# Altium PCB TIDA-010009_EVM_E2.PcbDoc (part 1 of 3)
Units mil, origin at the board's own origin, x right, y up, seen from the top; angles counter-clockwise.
Board outline 4485 x 3050 mil, 4 copper layers (Top Layer, Signal Layer 1, Signal Layer 2, Bottom Layer), stack 61.634 mil thick; 216 components, 95 nets, 514 pads, 224 vias.
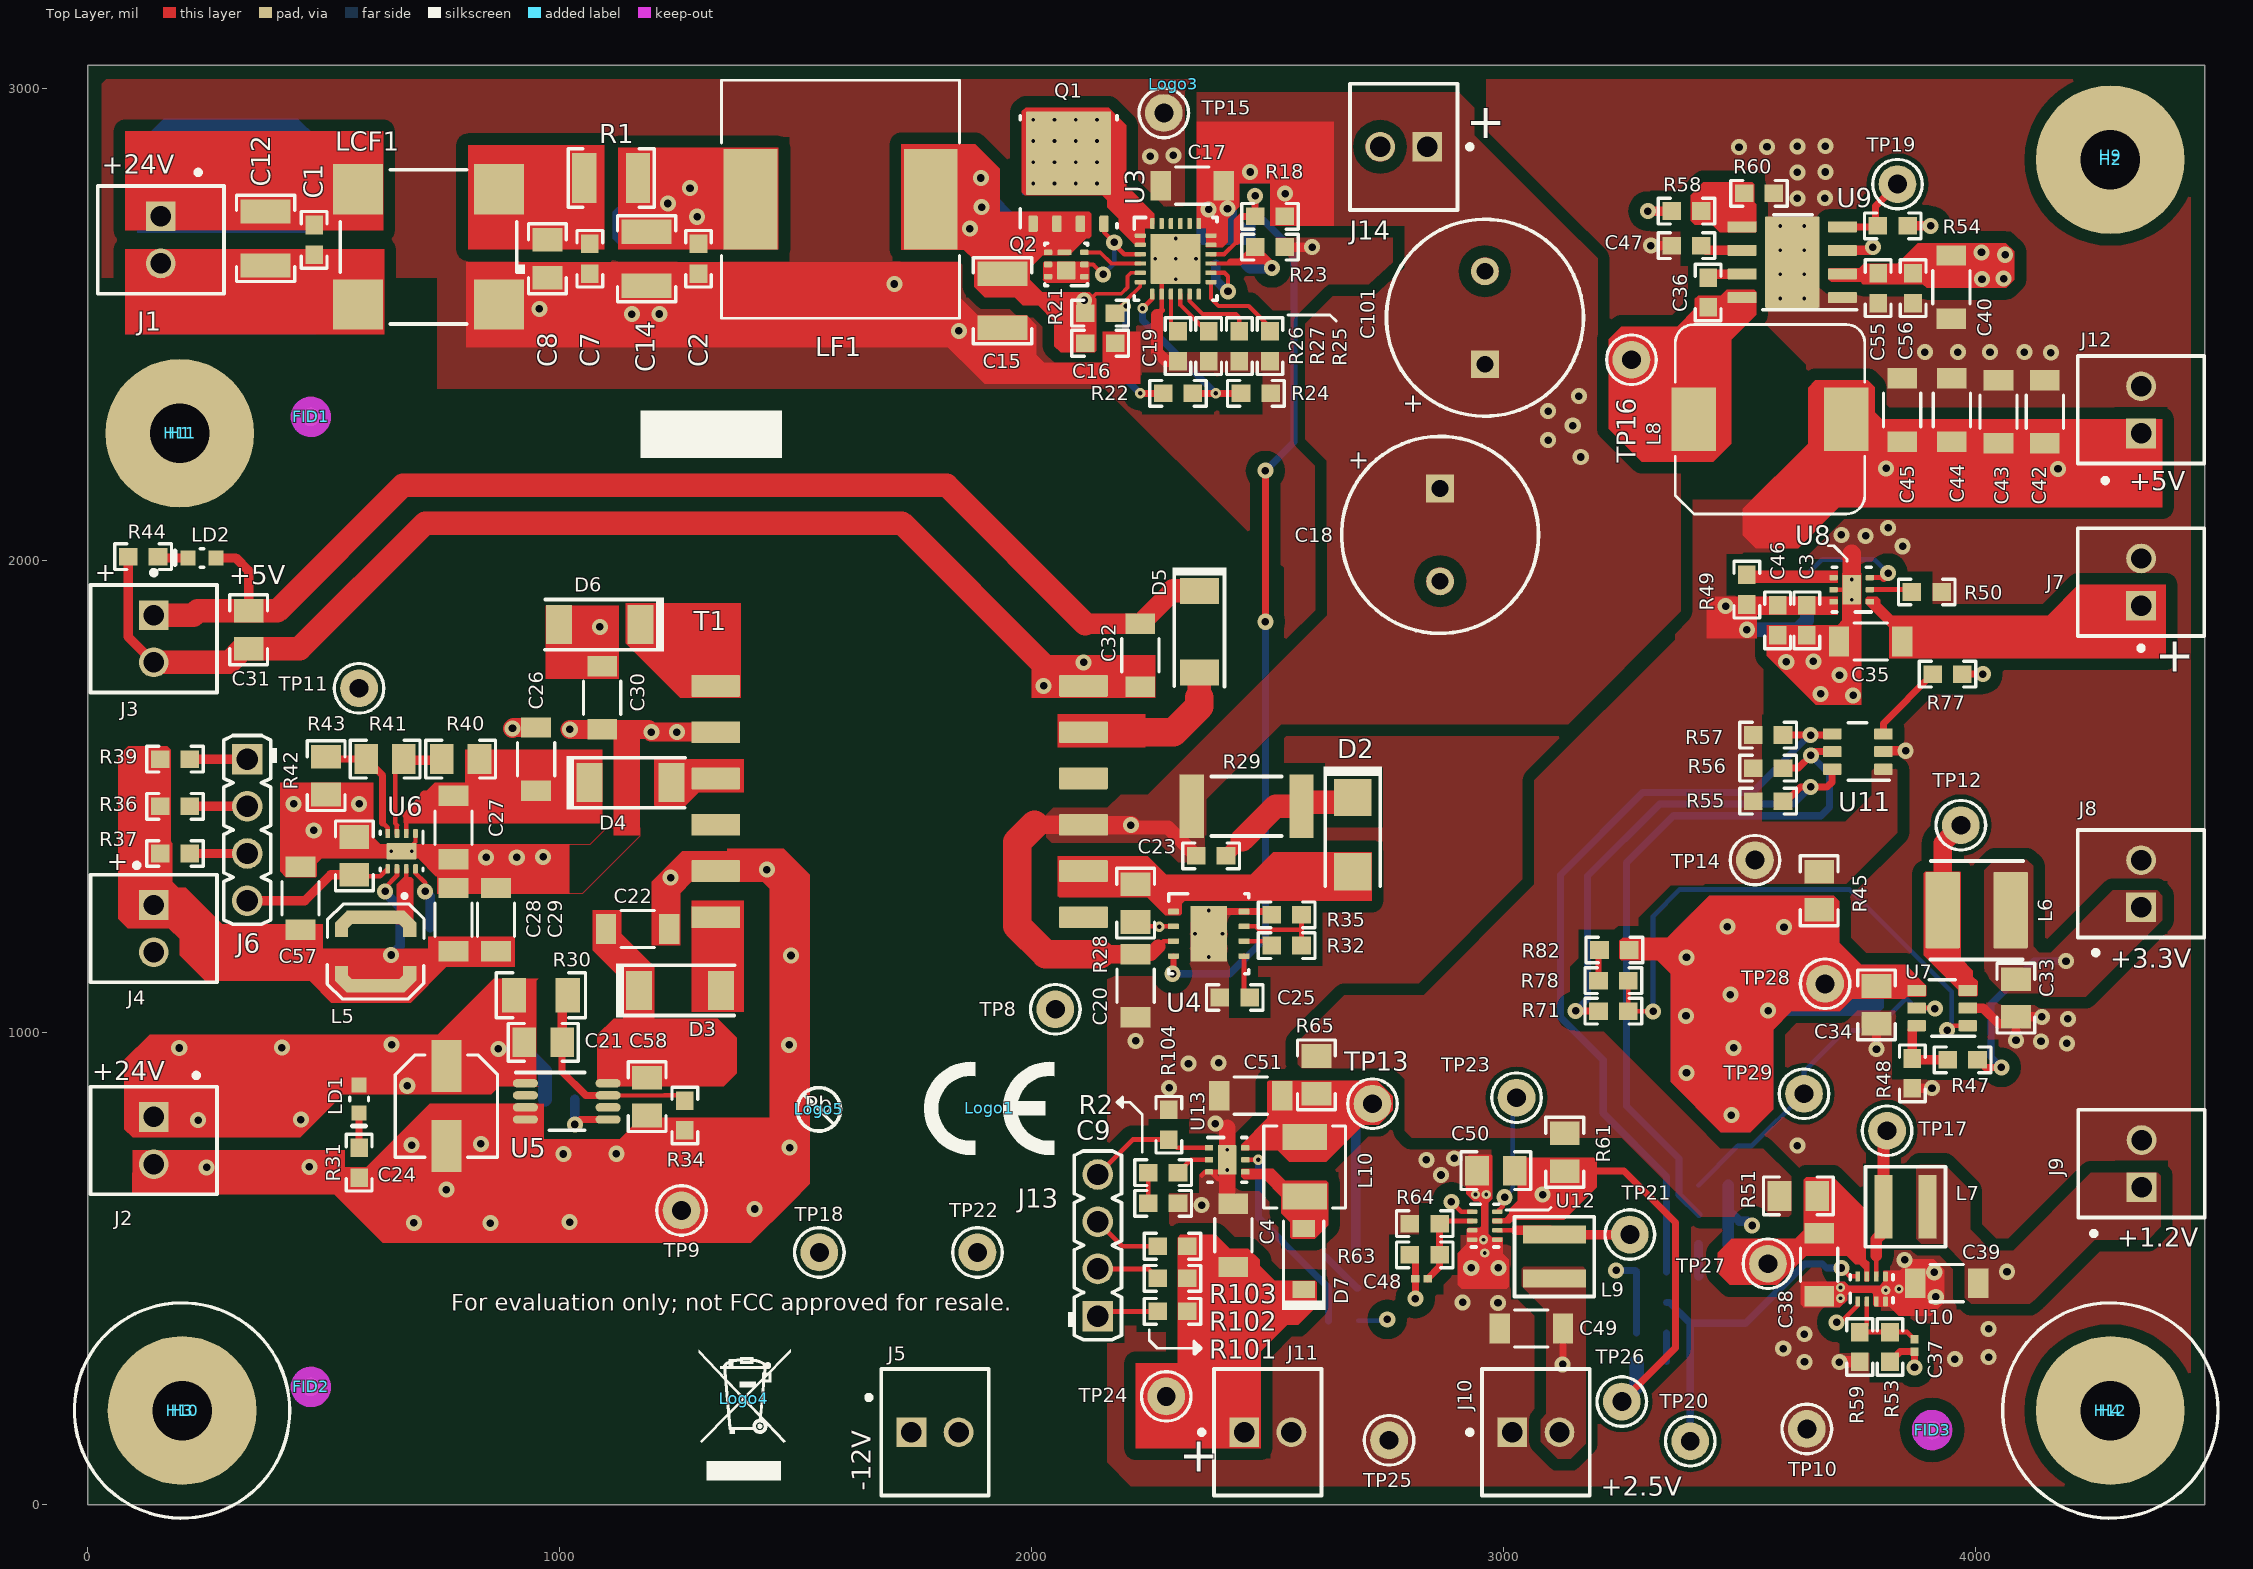
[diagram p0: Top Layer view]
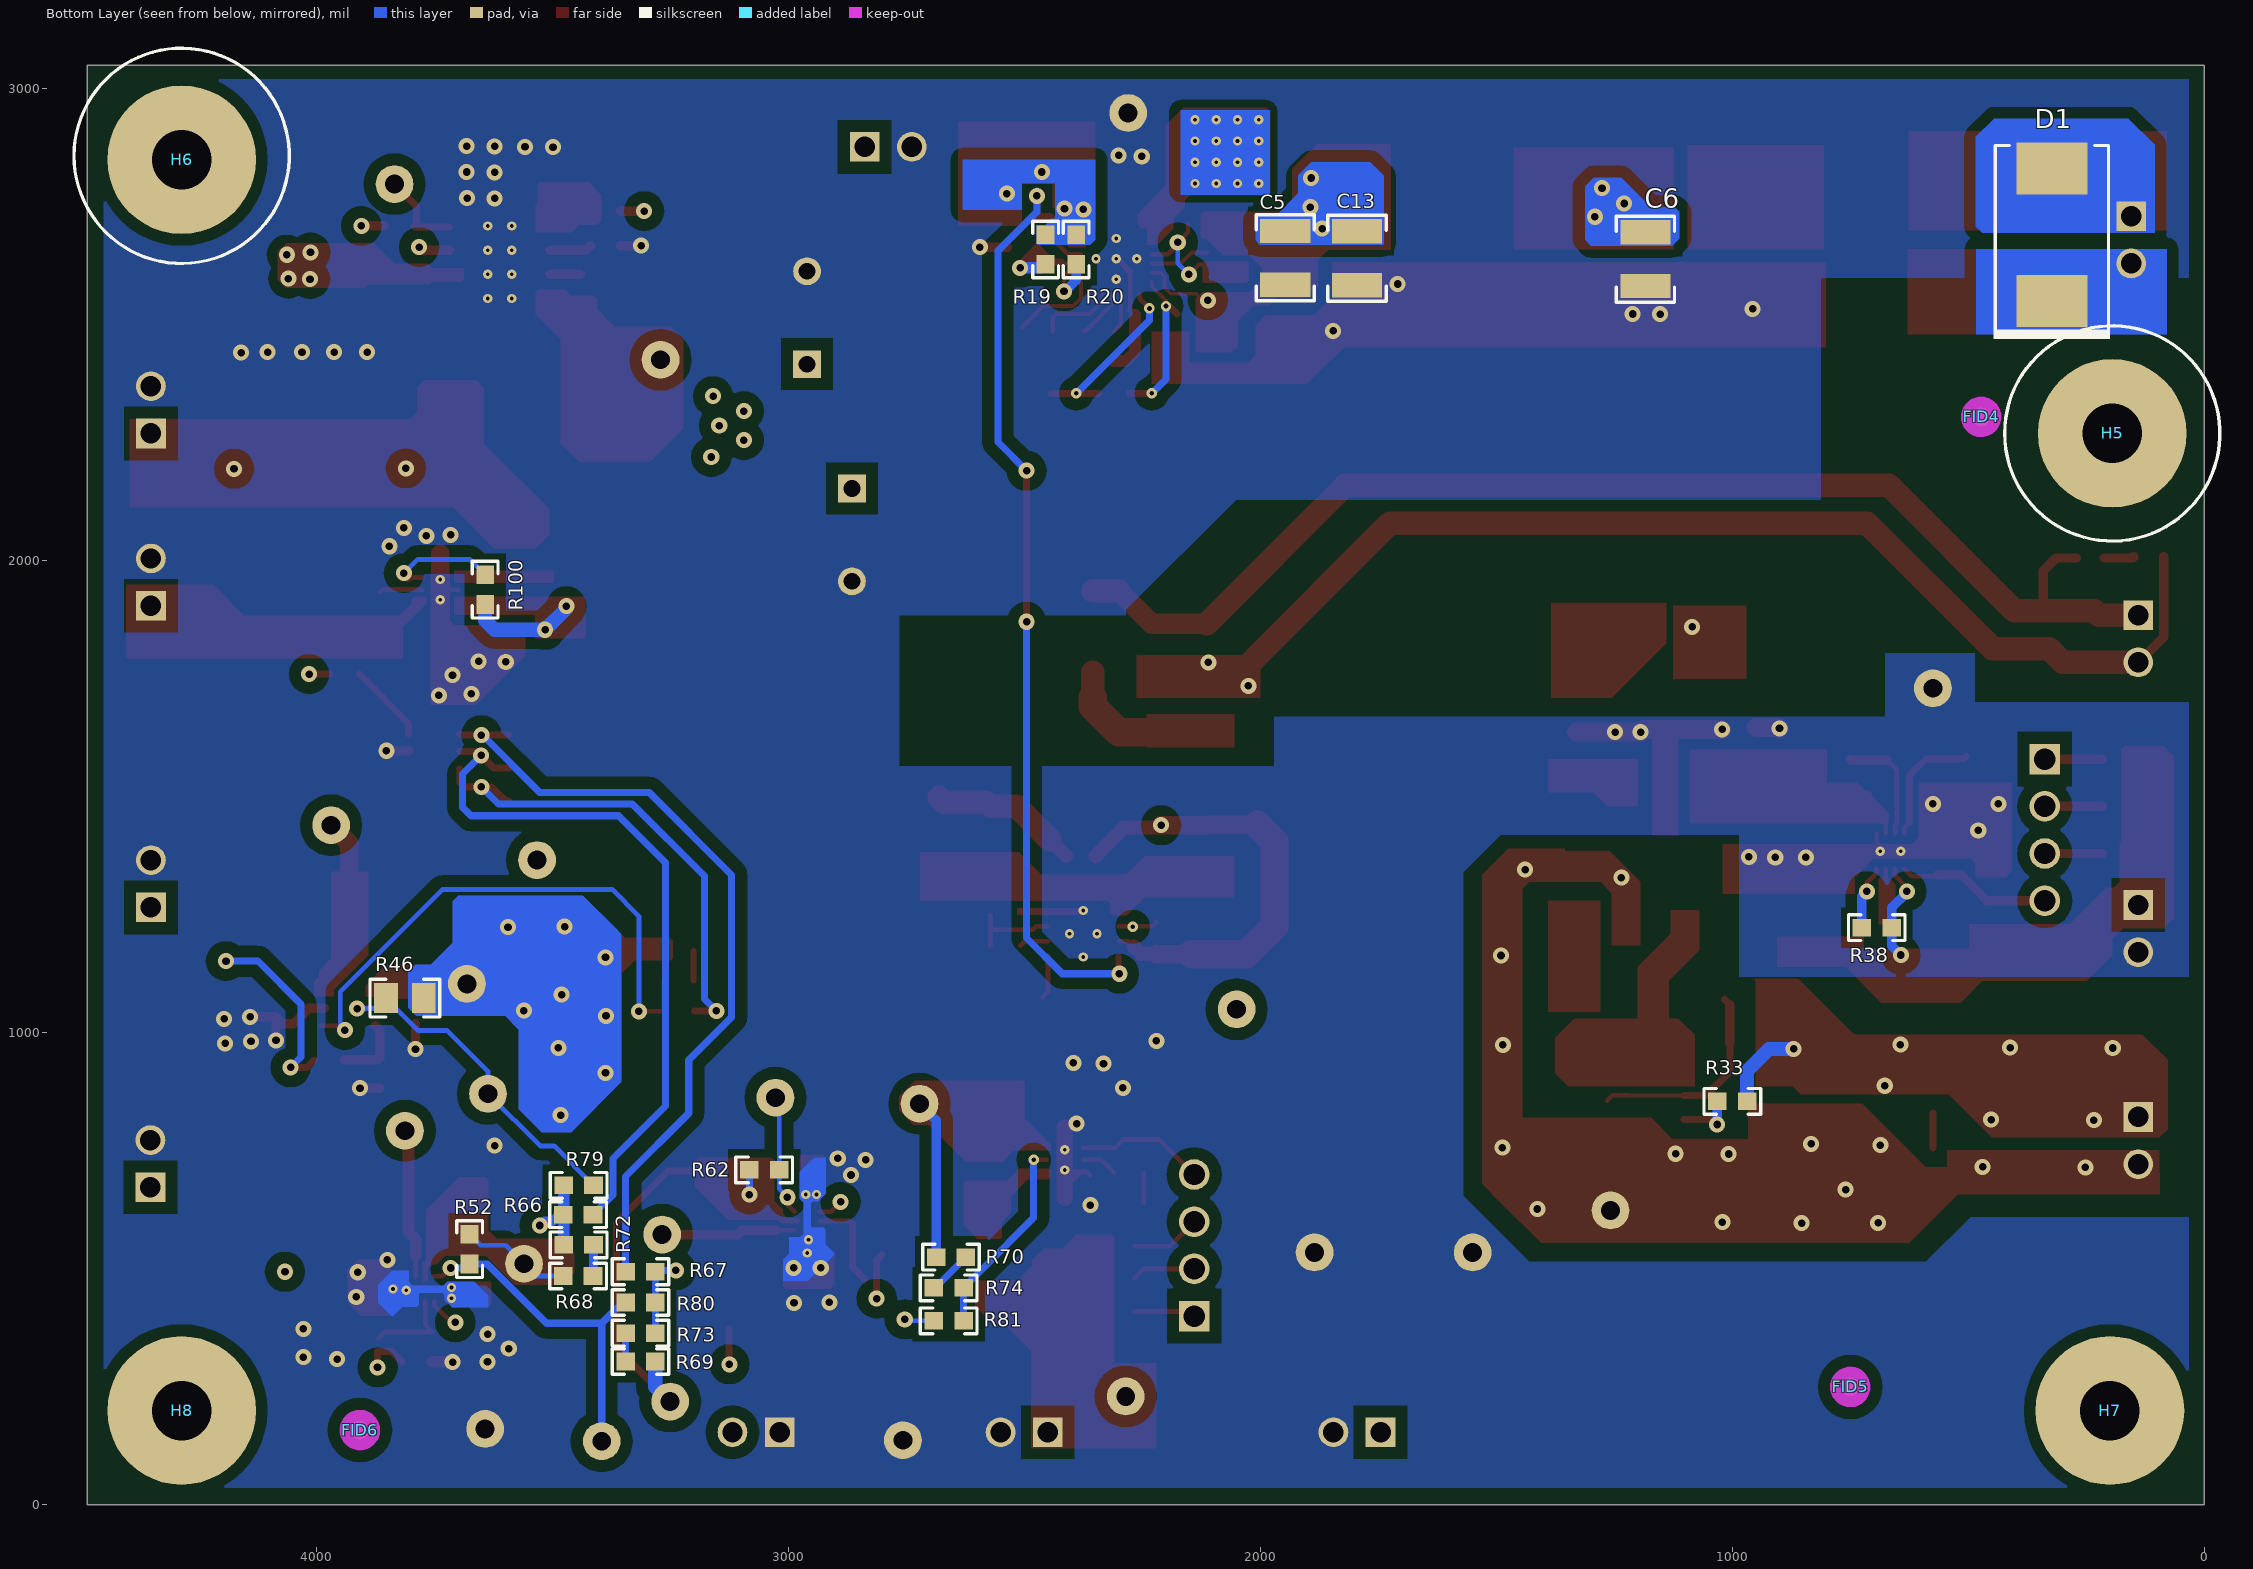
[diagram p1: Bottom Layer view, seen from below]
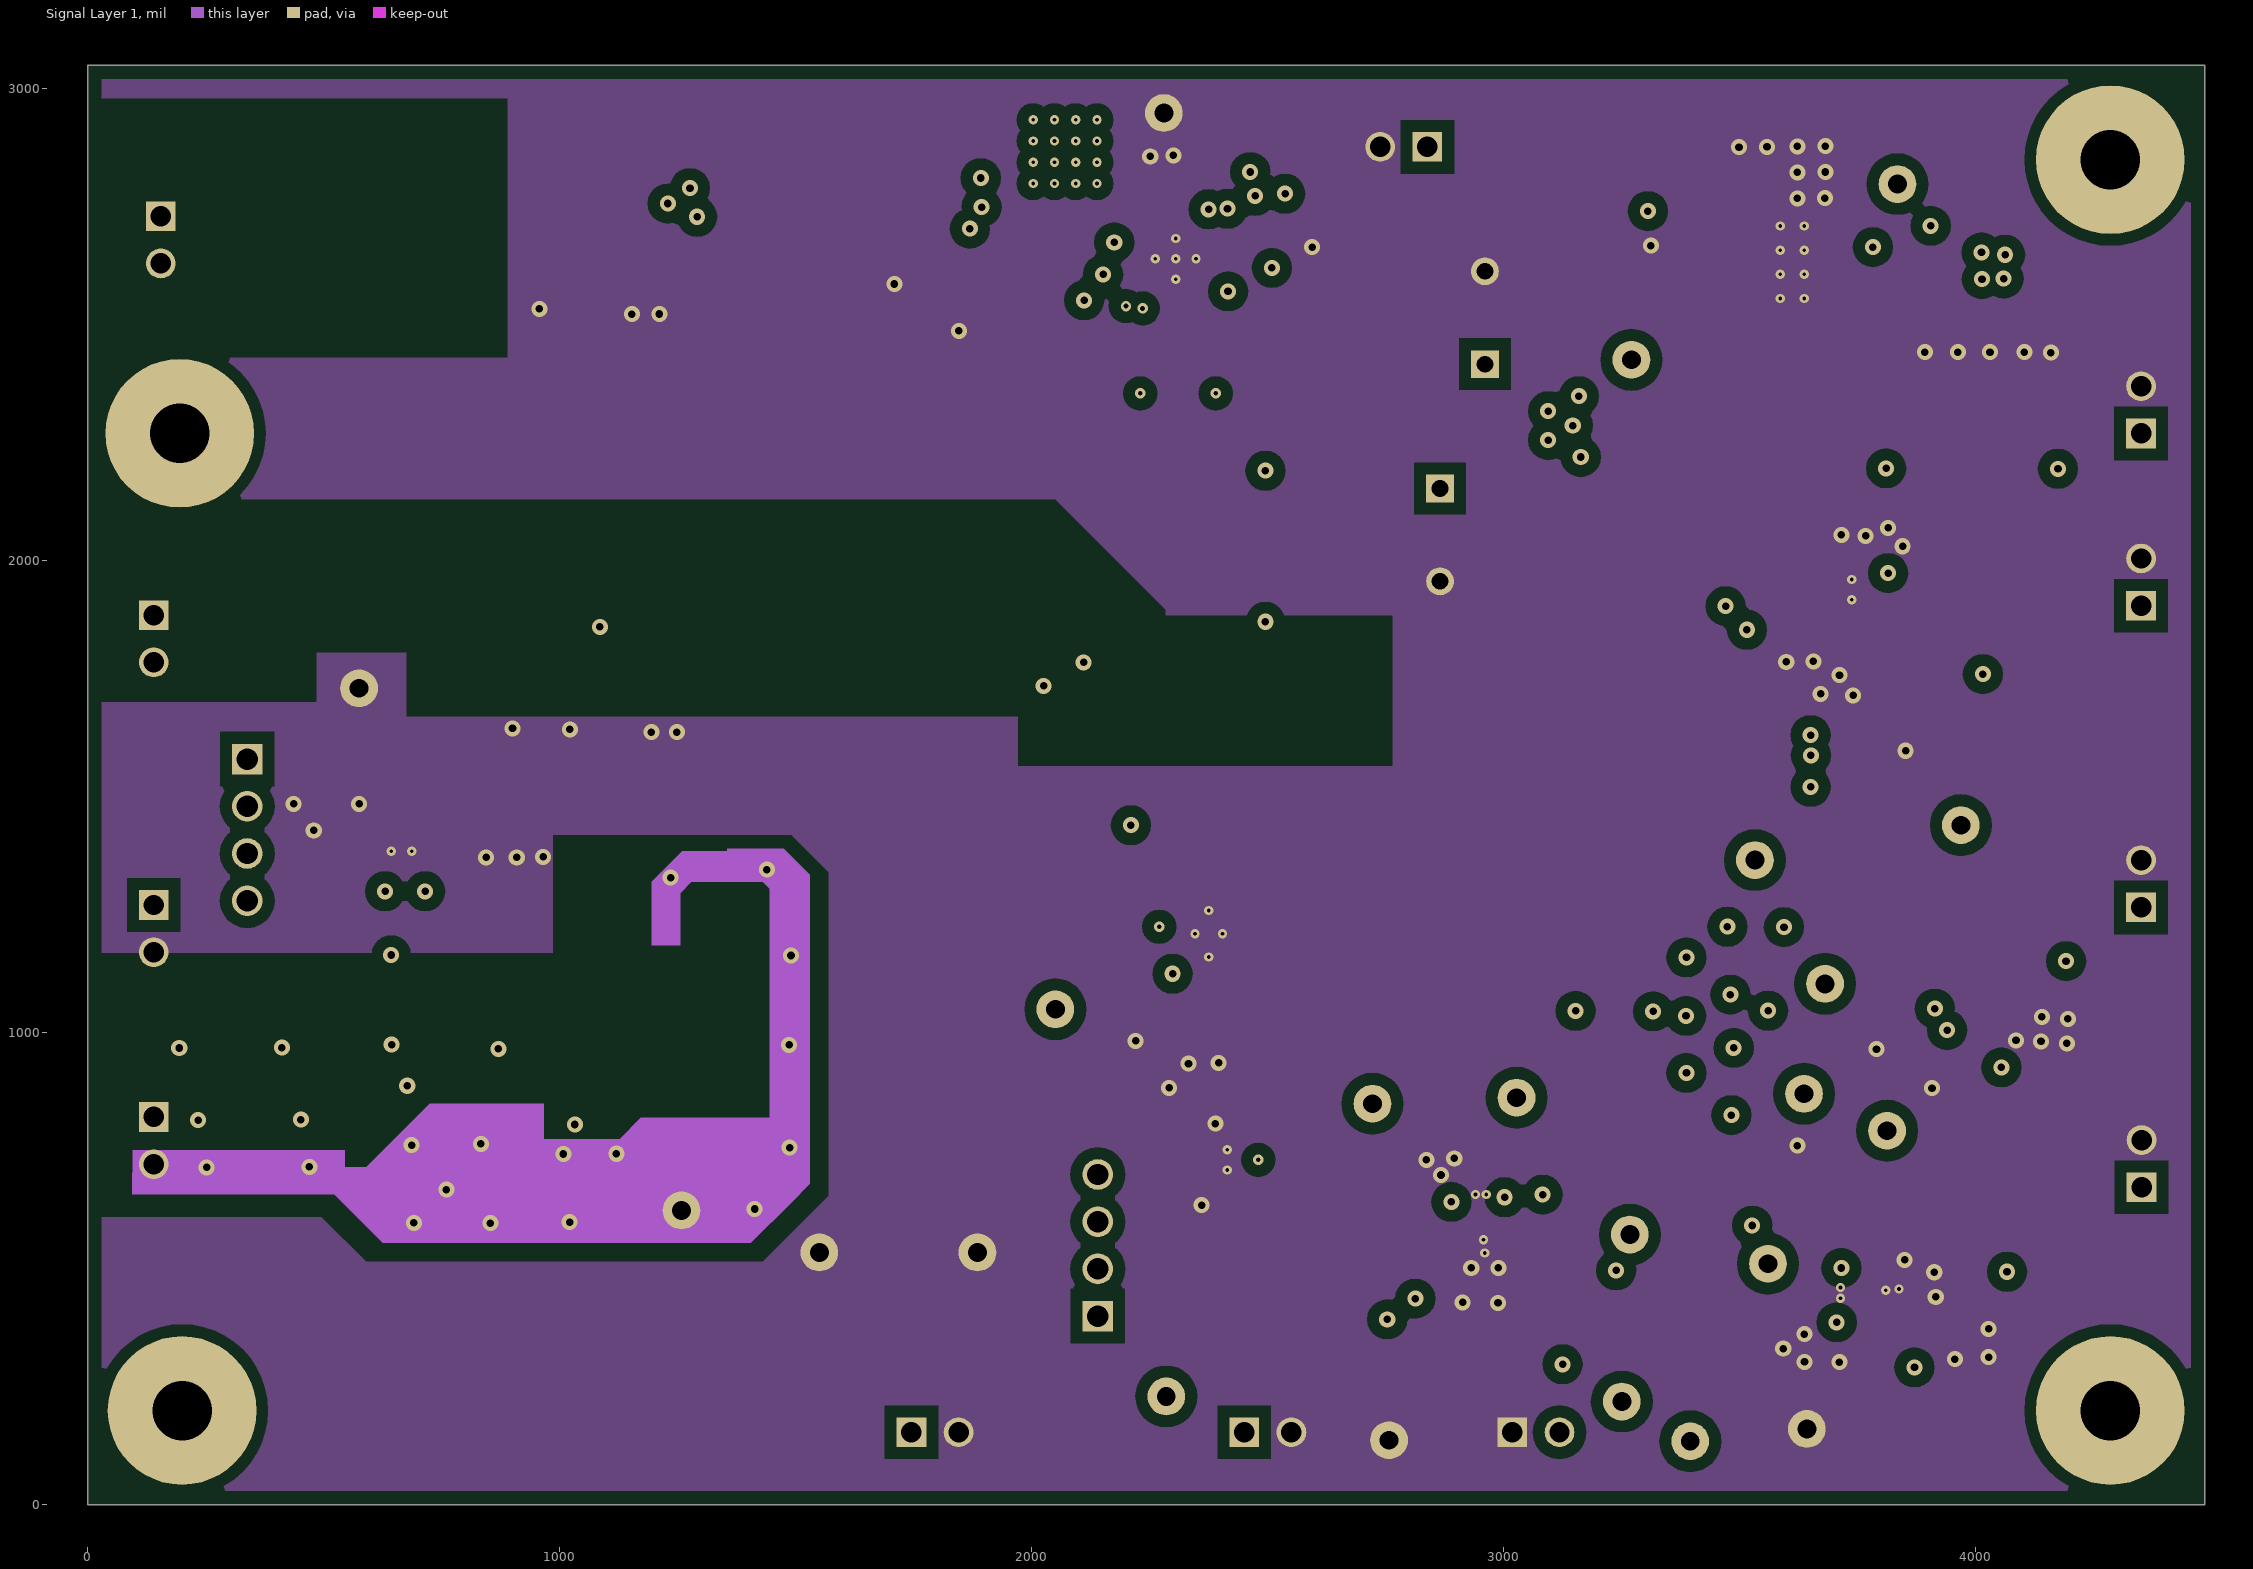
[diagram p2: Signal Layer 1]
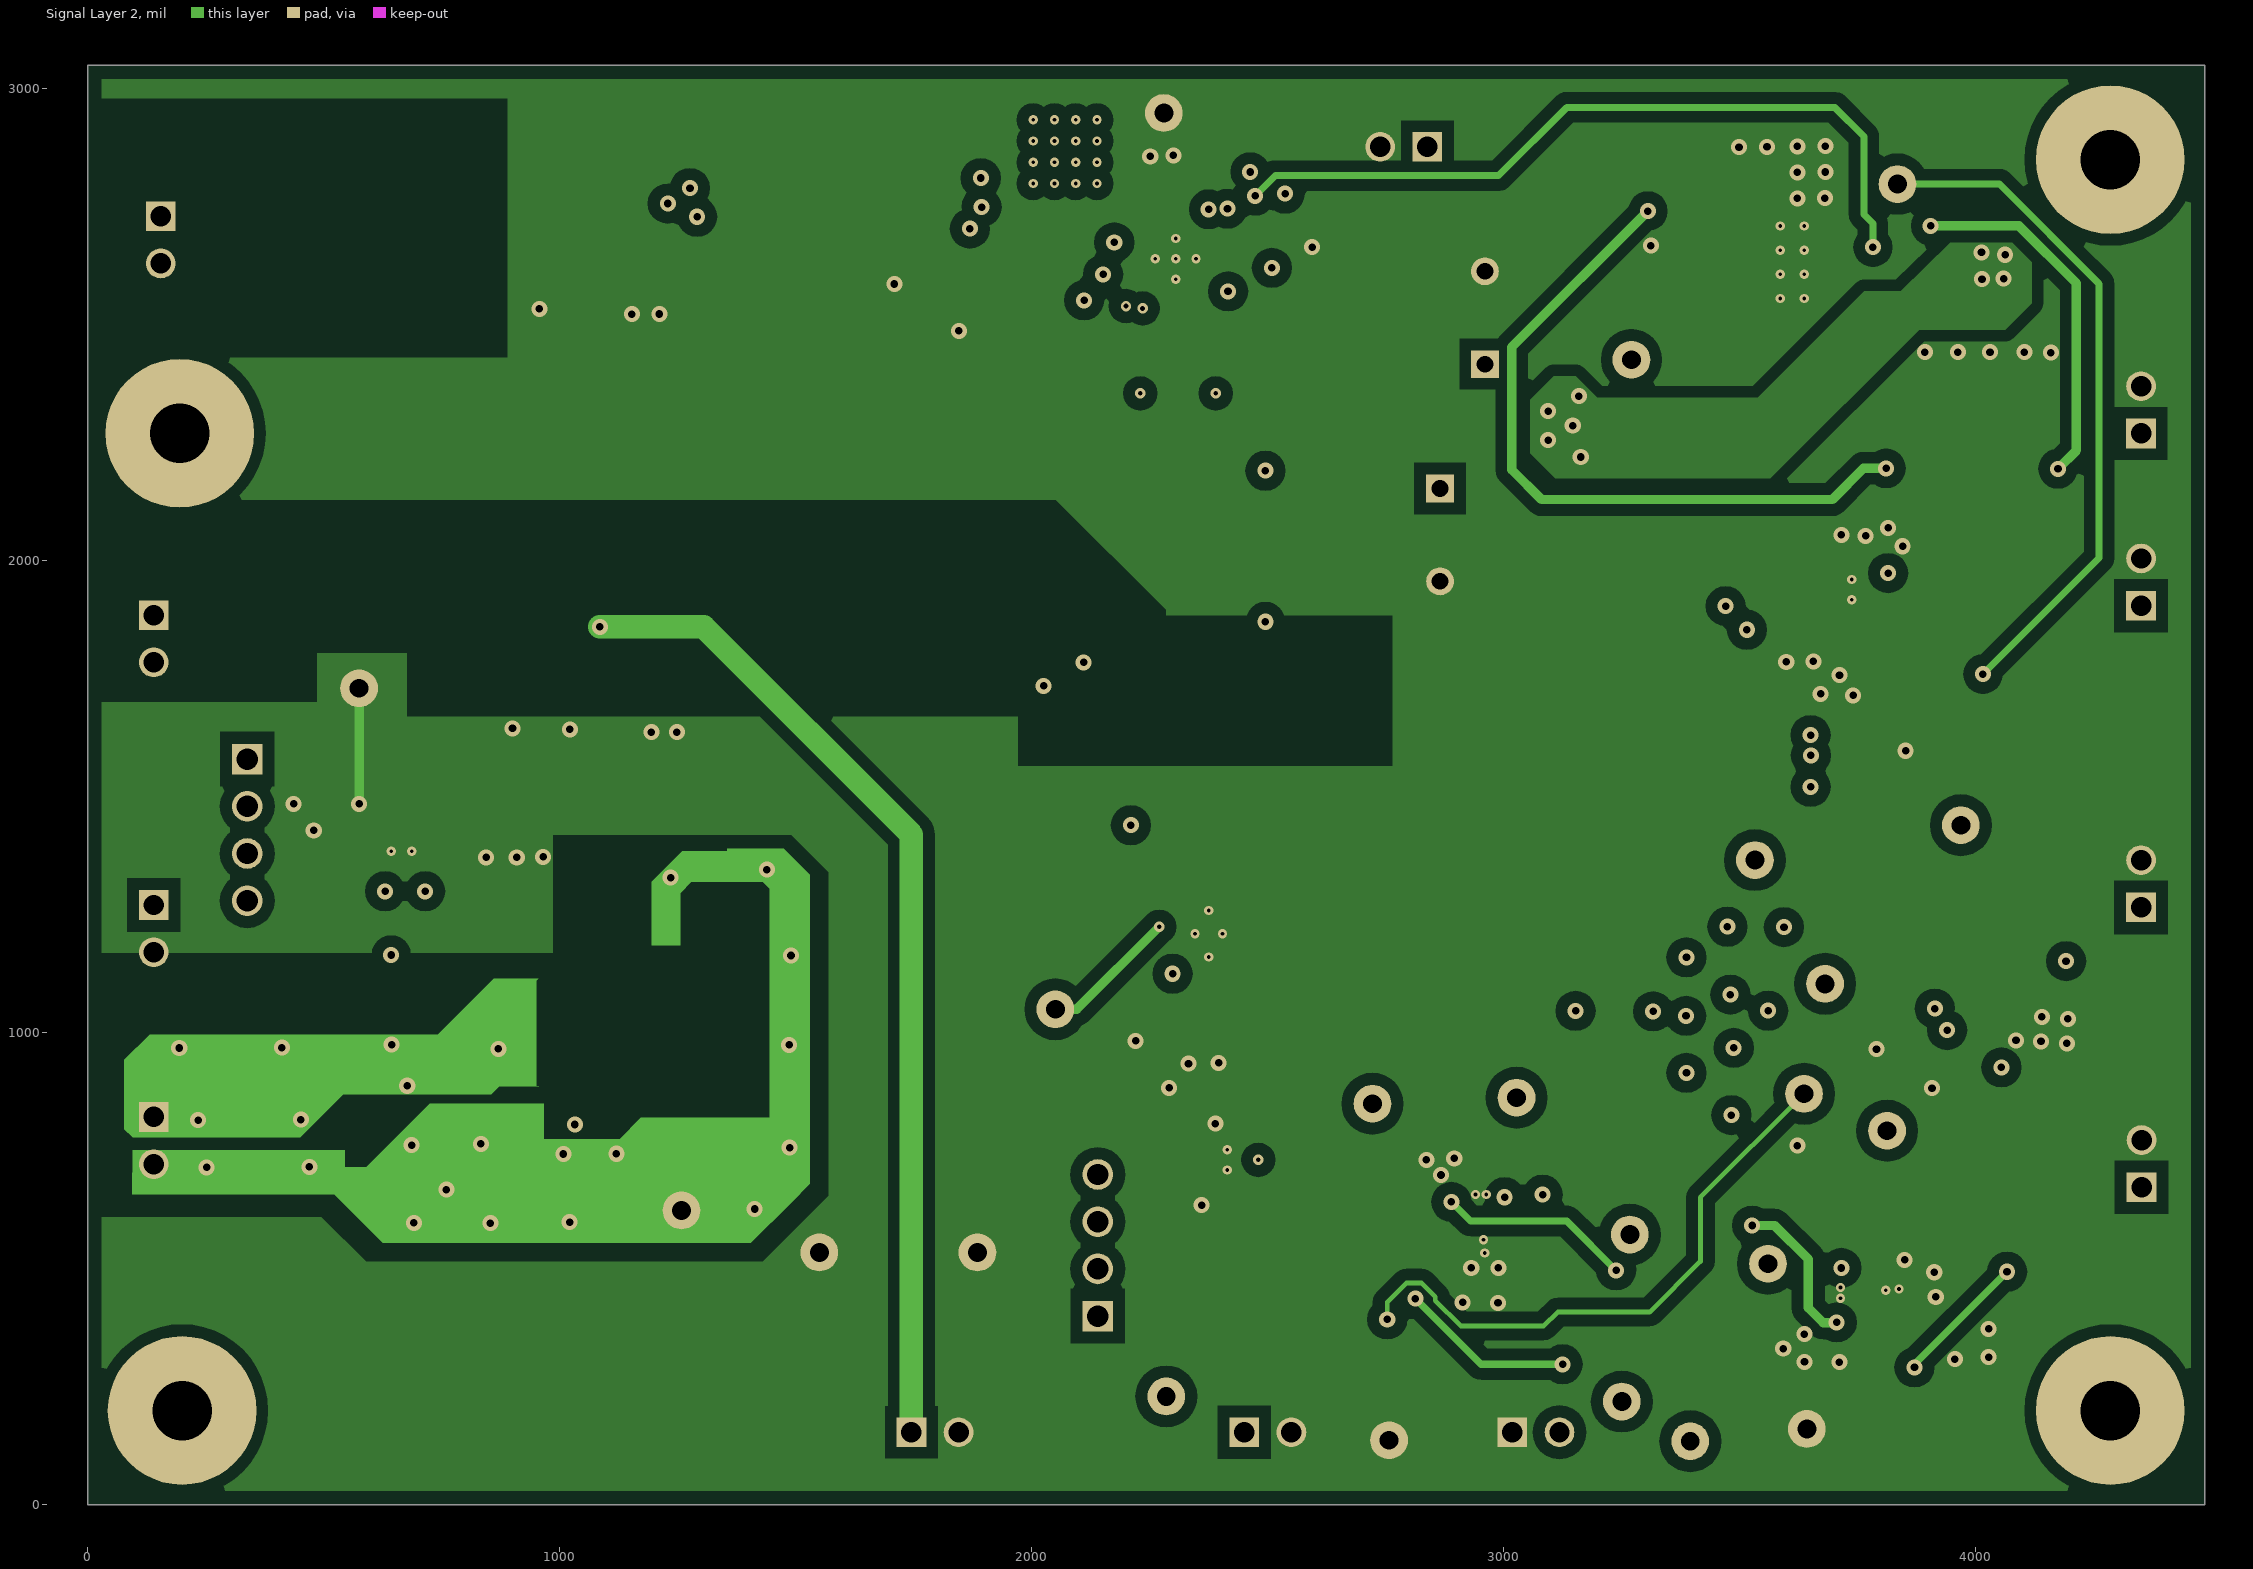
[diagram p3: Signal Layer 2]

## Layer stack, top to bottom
Top Solder: solder mask 0.4, Solder Resist, Dk 3.5
Top Layer: signal copper 1.4
Dielectric 2: dielectric 14, FR-4 High Tg, Dk 4.2
Signal Layer 1: signal copper 1.417
Dielectric1: core 28, FR-4 High Tg, Dk 4.8
Signal Layer 2: signal copper 1.417
Dielectric 3: dielectric 14, FR-4 High Tg, Dk 4.2
Bottom Layer: signal copper 1.4
Bottom Solder: solder mask 0.4, Solder Resist, Dk 3.5

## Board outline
0,0 4485,0 4485,3050 0,3050

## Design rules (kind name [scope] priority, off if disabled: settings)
AcuteAngle [All] p1: minimum=4.50000000000000E+0001 checktracksonly=FALSE
AssemblyTestPointUsage [All] p1: valid=2
BoardOutlineClearance [OnCopper and IsPoly] p1: gap=30 ignorepadtopadclearanceinfootprint=FALSE
Clearance Clearance_Keepouts [((IsTrack Or IsArc) And Not InPoly) And IsFree and IsKeepOut vs ((IsTrack Or IsArc) And Not InPoly) And IsFree and IsKeepOut] p1: gap=0 ignorepadtopadclearanceinfootprint=FALSE
Clearance Clearance_Poly [InPolygon] p2: gap=25 ignorepadtopadclearanceinfootprint=FALSE except(0: Arc-Hole Track-Hole SMDPad-Hole THPad-Hole Via-Hole Fill-Hole Poly-Hole Region-Hole Text-Hole; 20: Arc-SMDPad Track-SMDPad)
Clearance Clearance_FiducialMark [IsKeepOut and InComponentClass('FiducialMark') vs IsPad and InComponentClass('FiducialMark')] p3: gap=0 ignorepadtopadclearanceinfootprint=FALSE
Clearance [All] p4: gap=7.87 ignorepadtopadclearanceinfootprint=FALSE except(0: Arc-Hole Track-Hole SMDPad-Hole THPad-Hole Via-Hole Fill-Hole Poly-Hole Region-Hole Text-Hole)
ComponentClearance ComponentClearance_MountingHoles_FiducialMarks [InComponentClass('Mounting Holes') vs InComponentClass('FiducialMark')] p1: gap=50 collisioncheckmode=3 verticalgap=10 showdistances=FALSE
ComponentClearance ComponentClearance_Shunt [InComponentClass('Header') vs InComponentClass('Shunt')] p2: gap=0 collisioncheckmode=3 verticalgap=0 showdistances=FALSE
ComponentClearance ComponentClearance_Logo [InComponentClass('Logo')] p3: gap=50 collisioncheckmode=3 verticalgap=10 showdistances=FALSE
ComponentClearance ComponentClearance_ScrewToNut [(HasFootprint('NY PMS 440 0025 PH')) vs (HasFootprint('Keystone_1902C'))] p4: gap=5 collisioncheckmode=3 verticalgap=10 showdistances=FALSE
ComponentClearance ComponentClearance_MountingHoles [InComponentClass('Mounting Holes')] p5: gap=100 collisioncheckmode=3 verticalgap=100000 showdistances=FALSE
ComponentClearance ComponentClearance_SmallPassives [HasFootprint('0201*') or HasFootprint('0402*') or HasFootprint('0508') or HasFootprint('0603*') or HasFootprint('0612') or HasFootprint('0805*') or HasFootprint('0815*') or HasFootprint('0830*') or HasFootprint('1206*') or HasFootprint('1210*') or HasFootprint('1808*') or HasFootprint('1812*') or HasFootprint('1825*') or HasFootprint('2010*') or HasFootprint('2220*') or HasFootprint('2225*') or HasFootprint('2512*') or HasFootprint('2728*') or HasFootprint('3518*') vs HasFootprint('0201*') or HasFootprint('0402*') or HasFootprint('0508') or HasFootprint('0603*') or HasFootprint('0612') or HasFootprint('0805*') or HasFootprint('0815*') or HasFootprint('0830*') or HasFootprint('1206*') or HasFootprint('1210*') or HasFootprint('1808*') or HasFootprint('1812*') or HasFootprint('1825*') or HasFootprint('2010*') or HasFootprint('2220*') or HasFootprint('2225*') or HasFootprint('2512*') or HasFootprint('2728*') or HasFootprint('3518*')] p6: gap=14.96 collisioncheckmode=3 verticalgap=10 showdistances=FALSE
ComponentClearance ComponentClearance_THtoSMT [IsThruComponent vs IsSMTComponent] p7: gap=20 collisioncheckmode=3 verticalgap=30 showdistances=FALSE
ComponentClearance ComponentClearance_THtoTH [IsThruComponent vs IsThruComponent] p8: gap=20 collisioncheckmode=3 verticalgap=30 showdistances=FALSE
ComponentClearance [All] p9: gap=30 collisioncheckmode=3 verticalgap=10 showdistances=FALSE
DiffPairsRouting [All] p1: maxlimit=100 minlimit=10 mostfreqgap=10 toplayer_minwidth=15 toplayer_maxwidth=15 toplayer_prefwidth=15 midlayer1_minwidth=15 midlayer1_maxwidth=15 midlayer1_prefwidth=15 midlayer2_minwidth=15 midlayer2_maxwidth=15 midlayer2_prefwidth=15 bottomlayer_minwidth=15 bottomlayer_maxwidth=15 bottomlayer_prefwidth=15 maxuncoupledlength=1000
FabricationTestPointUsage TestPointUsage [All] p1: valid=2 allowmultiple=FALSE
FabricationTestpoint Testpoint [All] p1: side=3 testpointundercomponent=TRUE minsize=40 maxsize=100 preferedsize=60 minholesize=0 maxholesize=40 preferedholesize=32 testpointgrid=1 allowsidetop=TRUE allowsidebottom=TRUE usegrid=TRUE gridtolerance=0.01
FanoutControl Fanout_LCC [IsLCC] p1: bgadir=Out bgaviamode=Centered fanoutstyle=Auto fanoutdirection=Alternating viagrid=1 // Fanout_LCC (Default Rule)
FanoutControl Fanout_BGA [IsBGA] p2: bgadir=Out bgaviamode=Centered fanoutstyle=Auto fanoutdirection=Alternating viagrid=1 // Fanout_BGA (Default Rule)
FanoutControl Fanout_Default [All] p4: bgadir=Out bgaviamode=Centered fanoutstyle=Auto fanoutdirection=Alternating viagrid=1 // Fanout_Default (Default Rule)
FanoutControl Fanout_Small [(CompPinCount < 5)] p5: bgadir=Out bgaviamode=Centered fanoutstyle=Auto fanoutdirection=OutThenIn viagrid=1 // Fanout_Small (Default Rule)
HoleSize [All] p1: absolutevalues=TRUE maxlimit=251 minlimit=7.87 maxpercent=80.000 minpercent=20.000
MinimumAnnularRing MinimumAnnularRing_ThermalPadVias [IsVia and InAnyComponent] p1: minimumring=5.91
MinimumAnnularRing [All] p2: minimumring=6
MinimumSolderMaskSliver MinimumSolderMaskSliver_Logo [InComponentClass('Logo') vs InComponentClass('Logo')] p1: minsoldermaskwidth=0.7
MinimumSolderMaskSliver [All] p2: minsoldermaskwidth=3.94
PlaneConnect [All] p1: planeconnectstyle=Direct reliefexpansion=10 reliefentries=4 reliefconductorwidth=10 reliefairgap=10
PolygonConnect [All] p1: connectstyle=Direct reliefconductorwidth=10 reliefentries=4 polygonreliefangle="90 Angle" airgapwidth=10
RoutingVias ThermalPadVias [IsVia and InAnyComponent] p1: holewidth=7.87 width=19.68 viastyle="Through Hole" minholewidth=7.87 minwidth=19.68 maxholewidth=12.99 maxwidth=23.62
RoutingVias [All] p2: holewidth=16 width=34 viastyle="Through Hole" minholewidth=7.87 minwidth=22 maxholewidth=40 maxwidth=65
SilkToBoardRegionClearance [Not ((IsComment or IsDesignator) And (Hide <> 'False')) and not InRegion(1000,500,4000,800)] p1:
SilkToSilkClearance SilkToSilkClearance_Pb-FreeLogo [(HasFootprint('Pb-Free_Overlay_Medium') OR HasFootprint('Pb-Free_Overlay_Small')) vs (HasFootprint('Pb-Free_Overlay_Medium') OR HasFootprint('Pb-Free_Overlay_Small'))] p1: silktosilkclearance=0
SilkToSilkClearance [All] p2: silktosilkclearance=4
SilkToSolderMaskClearance SilkToComponentPadClearance [(IsPad or IsFill or IsRegion) and InAnycomponent] p1: minsilkscreentomaskgap=5 clearancetoexposedcopper=TRUE
SilkToSolderMaskClearance "Silk to Solder Mask Opening" [All] p2: minsilkscreentomaskgap=4 clearancetoexposedcopper=FALSE
SolderMaskExpansion [All] p1: expansion=1.97
Width [All] p1: maxlimit=100 minlimit=6 preferedwidth=20 checkconnectedcopper=TRUE
15 further rules are at their usual default settings.

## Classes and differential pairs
component class "Mounting Holes": H1 H2 H3 H4
component class PCB_Project_EVM_Hardware: FID1 FID2 FID3 FID4 FID5 FID6 H1 H2 H3 H4 H5 H6 H7 H8 H9 H10 H11 H12 Logo1 Logo3 Logo4 Logo5 ZZ1 ZZ2 ZZ3 ZZ4
component class FiducialMark: FID1 FID2 FID3 FID4 FID5 FID6
component class AssemblyNote: ZZ1 ZZ2 ZZ3 ZZ4
component class Header: J6 J13
component class Schematic1: C1 C2 C5 C6 C7 C8 C12 C13 C14 C15 C16 C17 C18 C19 C20 C21 C22 C23 C24 C25 C26 C27 C28 C29 C30 C31 C32 C57 C58 C101 D1 D2 D3 D4 D5 D6 J1 J2 J3 J4 J5 J6 J14 L5 LCF1 LD1 LD2 LF1 Q1 Q2 R1 R18 R19 R20 R21 R22 R23 R24 R25 R26 R27 R28 R29 R30 R31 R32 R33 R34 R35 R36 R37 R38 R39 R40 R41 R42 R43 R44 T1 TP8 TP9 TP10 TP11 U3 U4 U5 U6
component class Schematic2: C3 C4 C9 C33 C34 C35 C36 C37 C38 C39 C40 C42 C43 C44 C45 C46 C47 C48 C49 C50 C51 C55 C56 D7 J7 J8 J9 J10 J11 J12 J13 L6 L7 L8 L9 L10 R2 R45 R46 R47 R48 R49 R50 R51 R52 R53 R54 R55 R56 R57 R58 R59 R60 R61 R62 R63 R64 R65 R66 R67 R68 R69 R70 R71 R72 R73 R74 R77 R78 R79 R80 R81 R82 R100 R101 R102 R103 R104 TP12 TP13 TP14 TP15 TP16 TP17 TP18 TP19 TP20 TP21 TP22 TP23 TP24 TP25 TP26 TP27 TP28 TP29 U7 U8 U9 U10 U11 U12 U13

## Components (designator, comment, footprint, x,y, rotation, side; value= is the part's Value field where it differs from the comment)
C1 "GCJ188R72A104KA01D" 0603#1 480,2680 r90 top value=0.1uF
C2 "GCJ188R72A104KA01D" 0603#1 1294,2640 r90 top value=0.1uF
C3 "CMP-0006831-4" 0603#1 3642,1874.02 r270 top value=1uF
C4 "C3216X7R1V106K160AC" 1206_180 2427,571 r90 top value=10uF
C5 "C3225X7S2A475K200AE" 1210 1947,2641.95 r270 bottom value=4.7uF
C6 "C3225X7S2A475K200AE" 1210 1184,2639 r270 bottom value=4.7uF
C7 "GCJ188R72A104KA01D" 0603#1 1064,2640 r90 top value=0.1uF
C8 "C2012X7S2A105K125AB" 0805_HV#1 974,2640 r270 top value=1uF
C9 "C0603C681K5RACTU" 0603#1 2278.27,639 r0 top value=680pF
C12 "C3225X7S2A475K200AE" 1210 377,2683 r270 top value=4.7uF
C13 "C3225X7S2A475K200AE" 1210 1795,2641 r270 bottom value=4.7uF
C14 "C3225X7S2A475K200AE" 1210 1184,2640 r270 top value=4.7uF
C15 "C3225X7S2A475K200AE" 1210 1938,2551 r270 top value=4.7uF
C16 "GCJ188R72A104KA01D" 0603#1 2145,2461 r180 top value=0.1uF
C17 "C3216X7R1H225K160AB" 1206_180 2339.76,2794.76 r180 top value=2.2uF
C18 "ECA-1HM471" M_1000x2000 2865,2055 r270 top value=470uF
C19 "CMP-0007388-4" 0603#1 2309.76,2454.76 r270 top value=0.022uF
C20 "C3216X7R1H475K160AC" 1206_180 2220,1100 r270 top value=4.7uF
C21 "C0805C331K5RACTU" 0805_HV#1 965,980 r0 top value=330pF
C22 "C3216X7R1H475K160AC" 1206_180 1165,1220 r0 top value=4.7uF
C23 "GCM188R72A472KA37D" 0603#1 2380,1375 r180 top value=4700pF
C24 "EEE-FC1H4R7R" SM_RADIAL_C 760,845 r270 top value=4.7uF
C25 "GRM188R71H392KA01D" 0603#1 2430,1075 r180 top value=3900pF
C26 "C3216X7R1H475K160AC" 1206_180 950,1580 r270 top value=4.7uF
C27 "CL31B106KBHNNNE" 1206_180 775,1435 r270 top value=10uF
C28 "CL31B106KBHNNNE" 1206_180 775,1240 r90 top value=10uF
C29 "CL31B106KBHNNNE" 1206_180 865,1240 r90 top value=10uF
C30 "C3216X7R1H475K160AC" 1206_180 1090,1710 r270 top value=4.7uF
C31 "C0805C105K5RACTU" 0805_HV#1 341,1854 r90 top value=1uF
C32 "C3216X7R1H475K160AC" 1206_180 2230,1800 r90 top value=4.7uF
C33 "GRM21BR71A106KE51L" 0805_HV#1 4085,1073.81 r270 top value=10uF
C34 "CMP-0007885-2" 0805_HV#1 3789.51,1059.33 r270 top value=4.7uF
C35 "EMK316BB7226ML-T" 1206_190 3777,1829 r180 top value=22uF
C36 "CMP-0007044-5" 0603#1 3433,2568.62 r270 top value=0.1uF
C37 "GRM033R71E121KA01D" 0201 3870,338 r90 top value=120pF
C38 "CGA5L1X7R1V475K160AE" 1206_190 3668.09,508.7 r270 top value=4.7uF
C39 "EMK316BB7226ML-T" 1206_190 3938.09,469.7 r180 top value=22uF
C40 "C3216X7R1V106K160AC" 1206_180 3948,2580 r270 top value=10uF
C42 "EMK316BB7226ML-T" 1206_190 4146,2315.62 r90 top value=22uF
C43 "EMK316BB7226ML-T" 1206_190 4048,2315.62 r90 top value=22uF
C44 "EMK316BB7226ML-T" 1206_190 3949,2319.62 r90 top value=22uF
C45 "EMK316BB7226ML-T" 1206_190 3844,2319.62 r90 top value=22uF
C46 "EMK107B7104KA-T" 0603#1 3580,1874.02 r270 top value=0.1uF
C47 "CMP-0006831-4" 0603#1 3387.05,2667.77 r180 top value=1uF
C48 "GRM033R71E121KA01D" 0201 2825.5,479 r0 top value=120pF
C49 "EMK316BB7226ML-T" 1206_190 3058.45,373.7 r180 top value=22uF
C50 "CMP-0007885-2" 0805_HV#1 2983.13,708.17 r180 top value=4.7uF
C51 "UMK316AB7475KL-T" 1206_190 2464,866.92 r180 top value=4.7uF
C55 "CGA3E3X7R1H224K080AB" 0603#1 3793,2577.62 r270 top value=0.22uF
C56 "CGA3E3X7R1H224K080AB" 0603#1 3867,2577.62 r270 top value=0.22uF
C57 "CL31B106KBHNNNE" 1206_180 451,1285 r90 top value=10uF
C58 "C0805C105K5RACTU" 0805_HV#1 1185,865 r270 top value=1uF
C101 "ECA-1HM471" M_1000x2000 2960,2515 r90 top value=470uF
D1 "SMCJ36CA" SMC 323,2691 r90 bottom value=36V
D2 "B2100A-13-F" SMA 2680,1420 r270 top value=100V
D3 "PMEG10030ELPX" SOD-128 1255,1090 r0 top value=100V
D4 "PMEG10030ELPX" SOD-128 1150,1530 r0 top value=100V
D5 "PMEG10030ELPX" SOD-128 2355,1850 r270 top value=100V
D6 "PMEG10030ELPX" SOD-128 1085,1865 r180 top value=100V
D7 "MBR0540T1G" SOD-123 2576,521 r90 top value=40V
FID1 "Fiducial" Fiducial10-20 473,2305 r0 top
FID2 "Fiducial" Fiducial10-20 473,250 r0 top
FID3 "Fiducial" Fiducial10-20 3907.36,158.66 r0 top
FID4 "Fiducial" Fiducial10-20 473,2305 r0 bottom
FID5 "Fiducial" Fiducial10-20 750,250 r0 bottom
FID6 "Fiducial" Fiducial10-20 3907.36,158.66 r0 bottom
H1 "NY PMS 440 0025 PH" "NY PMS 440 0025 PH" 195,2270 r0 top locked
H2 "NY PMS 440 0025 PH" "NY PMS 440 0025 PH" 4285,2850 r0 top locked
H3 "NY PMS 440 0025 PH" "NY PMS 440 0025 PH" 200,200 r0 top locked
H4 "NY PMS 440 0025 PH" "NY PMS 440 0025 PH" 4285,200 r0 top locked
H5 "1902C" Keystone_1902C 195,2270 r180 bottom locked
H6 "1902C" Keystone_1902C 4285,2850 r180 bottom locked
H7 "1902C" Keystone_1902C 200,200 r180 bottom locked
H8 "1902C" Keystone_1902C 4285,200 r180 bottom locked
H9 "SJ-5303 (CLEAR)" Bumpon_SJ5003Transparent#1 4285,2858 r180 top
H10 "SJ-5303 (CLEAR)" Bumpon_SJ5003Transparent#2 200,200 r0 top
H11 "SJ-5303 (CLEAR)" Bumpon_SJ5003Transparent#1 195,2270 r180 top
H12 "SJ-5303 (CLEAR)" Bumpon_SJ5003Transparent#2 4285,200 r0 top
J1 "282834-2" TEC_282834-2 155,2680 r270 top
J2 "282834-2" TEC_282834-2 140,772 r270 top
J3 "282834-2" TEC_282834-2 140,1835 r270 top
J4 "282834-2" TEC_282834-2 140,1221 r270 top
J5 "282834-2" TEC_282834-2 1795,154 r0 top
J6 "61300411121" WURTH_61300411121 338,1430 r270 top
J7 "282834-2" TEC_282834-2 4350,1955 r90 top
J8 "282834-2" TEC_282834-2 4350,1316 r90 top
J9 "282834-2" TEC_282834-2 4351,723 r90 top
J10 "282834-2" TEC_282834-2 3068,154 r0 top
J11 "282834-2" TEC_282834-2 2500,154 r0 top
J12 "282834-2" TEC_282834-2 4350,2320 r90 top
J13 "61300411121" WURTH_61300411121 2140,550 r90 top
J14 "282834-2" TEC_282834-2 2788,2877 r180 top
L5 "LPS4018-223MRB" LPS4018 610,1172.5 r270 top value=22uH
L6 "LQH5BPN2R2NT0L" LQH5BPN_20 4001.8,1260 r0 top value=2.2uH
L7 "XFL4015-471MEC" XFL4015 3851.09,631.7 r0 top value=470nH
L8 "7447798111" WE-PDF_1064 3564,2300 r0 top value=11uH
L9 "XFL4015-471MEC" XFL4015 3107.13,526.17 r270 top value=470nH
L10 "FDSD0420-H-100M" FDSD0420 2578,716 r270 top value=10uH
LCF1 "CMP-0076872-1" WE-SL5_HC 722,2665 r180 top value=11uH
LD1 "LG L29K-G2J1-24-Z" "LG L29K_GREEN" 575,860 r270 top value=Green
LD2 "LG L29K-G2J1-24-Z" "LG L29K_GREEN" 242,2006 r180 top value=Green
LF1 "SRR1260-4R7Y" SRR1260 1595,2766 r0 top value=4.7uH
Logo1 "CE Mark" CE_Mark_5mm 1910,840 r0 top
Logo3 "FCC disclaimer" FCC_disclaimer 2300,3010 r0 top
Logo4 "WEEE logo" WEEE_Minimum 1390,225 r0 top
Logo5 "Pb-Free Symbol" Pb-Free_Overlay_Small 1549,838 r0 top
Q1 "CSD19533Q5A" DQJ0008A 2078,2824.18 r90 top value=100V
Q2 "CSD16301Q2" DQK0006C 2073,2627.8 r180 top value=25V
R1 "MCR25JZHJ000" 1210 1109,2811 r0 top value=0
R2 "RG1608P-103-B-T5" 0603#1 2278.27,704 r0 top value=10.0k
R18 "RG1608P-103-B-T5" 0603#1 2504.76,2729.76 r0 top value=10.0k
R19 "RT0603DRE07499KL" 0603#2 2454.76,2659.76 r90 top value=499k
R20 "RG1608P-103-B-T5" 0603#2 2389.76,2659.76 r90 top value=10.0k
R21 "RC0603FR-07665KL" 0603#1 2144.76,2524.76 r180 top value=665k
R22 "RC0603FR-0714KL" 0603#1 2309.76,2354.76 r180 top value=14.0k
R23 "RT0603BRD0731K6L" 0603#1 2504.76,2664.76 r180 top value=31.6k
R24 "RG1608P-303-B-T5" 0603#1 2474.76,2354.76 r180 top value=30.0k
R25 "RG1608P-103-B-T5" 0603#1 2504.76,2454.76 r90 top value=10.0k
R26 "RG1608P-302-B-T5" 0603#1 2374.76,2454.76 r90 top value=3.00k
R27 "RMCF0603ZT0R00" 0603#1 2439.76,2454.76 r90 top value=0
R28 "CRCW0805365KFKEA" 0805_HV#1 2220,1275 r90 top value=365k
R29 "CRCW25126K20JNEG" 2512 2455,1480 r0 top value=6.2k
R30 "RC1206FR-072M05L" 1206 960,1080 r0 top value=2.05Meg
R31 "RC0603JR-0718KL" 0603#1 575,725 r90 top value=18k
R32 "RT0603DRE07562KL" 0603#1 2540,1185 r180 top value=562k
R33 "RC0603FR-07330KL" 0603#2 1000,855 r180 top value=330k
R34 "RC0603FR-07105KL" 0603#1 1265,825 r270 top value=105k
R35 "RT0603DRE0712K1L" 0603#1 2540,1250 r0 top value=12.1k
R36 "CRCW06031M05FKEA" 0603#1 185,1480 r180 top value=1.05Meg
R37 "CRCW06032M32FKEA" 0603#1 185,1380 r0 top value=2.32Meg
R38 "RT0603BRB071KL" 0603#2 694,1223 r180 top value=1.00k
R39 "CRCW06031M80JNEA" 0603#1 185,1580 r180 top value=1.8Meg
R40 "CRCW080512R1FKEA" 0805_HV#1 790,1580 r0 top value=12.1
R41 "RG2012P-152-B-T5" 0805_HV#1 630,1580 r0 top value=1.50k
R42 "RG2012P-204-B-T5" 0805_HV#1 565,1375 r270 top value=200k
R43 "ERJ-6GEYJ910V" 0805_HV#1 505,1545 r90 top value=91
R44 "RC0603JR-0718KL" 0603#1 117.5,2009 r180 top value=18k
R45 "ERJ-6GEY0R00V" 0805_HV#1 3668,1301 r270 top value=0
R46 "RR1220P-4753-D-M" 0805_HV#2 3812.07,1073.81 r180 top value=475k
R47 "RT0603DRE07453KL" 0603#1 3972,943 r0 top value=453k
R48 "ERA-3AEB104V" 0603#1 3865.55,914.36 r90 top value=100k
R49 "RG1608P-304-B-T5" 0603#1 3515,1939.02 r90 top value=300k
R50 "RC0603FR-07316KL" 0603#1 3896,1934.01 r180 top value=316k
R51 "ERJ-6GEY0R00V" 0805_HV#1 3624.09,654.7 r0 top value=0
R52 "ERA-3AEB104V" 0603#1 3675,542 r270 bottom value=100k
R53 "ERA-3AEB104V" 0603#1 3818.09,334.7 r270 top value=100k
R54 "ERA-3AEB104V" 0603#2 3824,2709.62 r180 bottom value=100k
R55 "ERA-3AEB104V" 0603#1 3560,1491 r180 top value=100k
R56 "ERA-3AEB104V" 0603#1 3560,1561 r180 top value=100k
R57 "ERA-3AEB104V" 0603#1 3560,1631 r180 top value=100k
R58 "ERA-3AEB104V" 0603#1 3387.05,2741.05 r180 top value=100k
R59 "ERA-3AEB104V" 0603#1 3754.09,334.7 r90 top value=100k
R60 "RT0603BRD0724K9L" 0603#1 3540.7,2778.39 r180 top value=24.9k
R61 "ERJ-6GEY0R00V" 0805_HV#1 3129.13,747.17 r270 top value=0
R62 "ERA-3AEB104V" 0603#1 3050.83,710 r180 bottom value=100k
R63 "RT0603DRE07475KL" 0603#1 2832.5,530 r180 top value=475k
R64 "RT0603BRD07150KL" 0603#1 2832.5,596 r0 top value=150k
R65 "ERJ-6GEY0R00V" 0805_HV#1 2603,911 r270 top value=0
R66 "RMCF0603ZT0R00" 0603#1 3445,615 r0 bottom value=0
R67 "RMCF0603ZT0R00" 0603#1 3313,494 r180 bottom value=0
R68 "ERA-3AEB104V" 0603#1 3445,485 r180 bottom value=100k
R69 "ERA-3AEB104V" 0603#1 3313,304 r0 bottom value=100k
R70 "ERA-3AEB104V" 0603#1 2655,525 r180 bottom value=100k
R71 "RMCF0603ZT0R00" 0603#1 3232.03,1046.16 r180 top value=0
R72 "RMCF0603ZT0R00" 0603#1 3444,551 r180 bottom value=0
R73 "RMCF0603ZT0R00" 0603#1 3313,364 r0 bottom value=0
R74 "RMCF0603ZT0R00" 0603#1 2660,460 r0 bottom value=0
R77 "RMCF0603ZT0R00" 0603#1 3940,1760 r0 top value=0
R78 "RMCF0603ZT0R00" 0603#1 3232.03,1110.64 r180 top value=0
R79 "RMCF0603ZT0R00" 0603#1 3444,677 r180 bottom value=0
R80 "RMCF0603ZT0R00" 0603#1 3313,429 r0 bottom value=0
R81 "RMCF0603ZT0R00" 0603#1 2660,390 r0 bottom value=0
R82 "ERA-3AEB104V" 0603#1 3234.15,1175.64 r180 top value=100k
R100 "RG1608P-304-B-T5" 0603#2 3642,1939 r90 top value=300k
R101 "CRCW0603187KFKEA" 0603#1 2298,410 r0 top value=187k
R102 "CRCW060371K5FKEA" 0603#1 2298,480 r0 top value=71.5k
R103 "CRCW060354K9FKEA" 0603#1 2298,548 r0 top value=54.9k
R104 "RG1608P-103-B-T5" 0603#1 2290.35,805.47 r270 top value=10.0k
T1 "750344009" Wurth_EFD15_4265 1720,1490 r180 top value=75uH
TP8 "5000" Keystone5000 2050,1050 r0 top
TP9 "5001" Keystone5001 1258,624 r180 top
TP10 "5001" Keystone5001 3642,161 r90 top
TP11 "5001" Keystone5001 575,1730 r90 top
TP12 "5000" Keystone5000 3968.26,1440 r180 top
TP13 "5000" Keystone5000 2721.8,850 r0 top
TP14 "5000" Keystone5000 3532,1366 r90 top
TP15 "5001" Keystone5001 2279.76,2948.77 r90 top
TP16 "5000" Keystone5000 3270.39,2426 r90 top
TP17 "5000" Keystone5000 3812,792.76 r180 top
TP18 "5001" Keystone5001 1550,535 r90 top
TP19 "5000" Keystone5000 3834,2798 r180 top
TP20 "5000" Keystone5000 3395,135 r90 top
TP21 "5000" Keystone5000 3267,572.82 r180 top
TP22 "5001" Keystone5001 1885,535 r180 top
TP23 "5000" Keystone5000 3027,862.74 r180 top
TP24 "5000" Keystone5000 2285,230 r180 top
TP25 "5001" Keystone5001 2757,137 r180 top
TP26 "5000" Keystone5000 3250,219 r0 top
TP27 "5000" Keystone5000 3559.64,511 r180 top
TP28 "5000" Keystone5000 3680.66,1104 r90 top
TP29 "5000" Keystone5000 3636,871 r180 top
U3 "TPS26630RGER" RGE0024H 2304.76,2639.76 r0 top
U4 "LM5180QNGURQ1" NGU0008C 2375,1210 r0 top
U5 "LP2951CMM/NOPB" DGK0008A_N 1015,855 r0 top
U6 "TPS62125DSGR" DSG0008A 665,1385 r270 top
U7 "TLV62569PDDC" DDC0006A_N 3928.78,1052.67 r180 top
U8 "TPS25200DRVR" DRV0006A 3737,1939 r180 top
U9 "LMR33630ADDAR" DDA0008J 3611,2632.62 r180 top
U10 "TPS62821DLCR" DLC0008A 3779.09,457.58 r90 top
U11 "LM3880MF-1AA" DBV0006A_N 3750,1596 r180 top
U12 "TPS62821DLCR" DLC0008A 2959.7,591.7 r0 top
U13 "TPS61170DRVR" DRV0006A 2413.98,731.04 r0 top
ZZ1 "This Assembly Note is for PCB labels only" AssemblyNoteLabel 185,3938 r0 top
ZZ2 "These assemblies are ESD sensitive, ESD precautions shall be observed." AssemblyNote 185,3829.11 r0 top
ZZ3 "These assemblies must be clean and free from flux and all contaminants. Use of no clean flux is not acceptable." AssemblyNote 185,3740.56 r0 top
ZZ4 "These assemblies must comply with workmanship standards IPC-A-610 Class 2, unless otherwise specified." AssemblyNote 185,3652 r0 top

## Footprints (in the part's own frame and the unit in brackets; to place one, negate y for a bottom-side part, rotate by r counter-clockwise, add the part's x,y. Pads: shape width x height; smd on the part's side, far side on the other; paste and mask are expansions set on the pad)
0201 [mm] "Data from Kemet datasheet CC101_COM dated 7/28/11"
  rect 0.46x0.42 smd mask+0.048: 1(-0.33,0) 2(0.33,0)
  body extent -0.31,-0.16 0.31,0.16, height 0.26
0603#1 [mm] "0603 from SM-752 data"
  rect 1x0.95 smd: 1(-0.8,0) 2(0.8,0)
  silkscreen extent -1.52,-0.69 1.52,0.69, body extent -0.87,-0.47 0.87,0.47, height 1
0603#2 [mm] "0603 from SM-752 data"
  rect 1x0.95 smd far side: 1(-0.8,0) 2(0.8,0)
  body extent -0.87,-0.47 0.87,0.47, height 1
0805_HV#1 [mil] "0805 with 30mil clearance between pads"
  rect 50x63 smd: 1(-40,0) 2(40,0)
  silkscreen extent -74,-40 74,40, body extent -43,-29 43,29, height 57
0805_HV#2 [mil] "0805 with 30mil clearance between pads"
  rect 50x63 smd far side: 1(-40,0) 2(40,0)
  body extent -43,-29 43,29, height 57
1206 [mm] "1206 from SM-752 data"
  rect 1.3x1.85 smd: 1(-1.45,0) 2(1.45,0)
  silkscreen extent -2.4,-1.21 2.4,1.21, body extent -1.7,-0.9 1.7,0.9, height 1.35
1206_180 [mm] "1206_180"
  rect 1.1x1.6 smd: 1(-1.7,0) 2(1.7,0)
  silkscreen extent -0.9,-1 0.9,1, body extent -1.75,-0.95 1.75,0.95, height 1.8
1206_190 [mm] "1206_190"
  rect 1.1x1.6 smd: 1(-1.7,0) 2(1.7,0)
  silkscreen extent -0.9,-1 0.9,1, body extent -1.75,-0.95 1.75,0.95, height 1.9
1210 [mm] "1210 from SM-752 data"
  rect 1.3x2.7 smd: 1(-1.45,0) 2(1.45,0)
  silkscreen extent -2.32,-1.57 2.32,1.57, body extent -1.7,-1.35 1.7,1.35, height 1.35
2512 [mm] "Chip Resistor, Body 6.3x3.2mm, IPC Medium Density"
  rect 1.3x3.4 smd: 1(-2.95,0) 2(2.95,0)
  silkscreen extent -1.9,-1.6 1.9,1.6, body extent -3.22,-1.67 3.22,1.67, height 0.71
AssemblyNote [mil] "Assembly Note"
AssemblyNoteLabel [mil] "Assembly Note for PCB Labels"
Bumpon_SJ5003Transparent#1 [mil] "3M Hemispherical Bumpon transparent"
  round 1 on Mech4: 0(0,0)
  body extent -219,-219 219,219, height 197
Bumpon_SJ5003Transparent#2 [mil] "3M Hemispherical Bumpon transparent"
  round 1 on Mech3: 0(0,0)
  silkscreen extent -228,-228 228,228, body extent -217,-218 219,218, height 197
CE_Mark_5mm [mil] "Minimum text height for CE Mark"
  silkscreen extent -138,-98 138,98
DBV0006A_N [mm] "SOT23, 6-Leads, Body 2.9x1.6mm, Pitch 0.95mm, Lead Span 2.8mm, IPC Medium Density"
  rrect17% 1x0.6 smd: 1(-1.375,0.95) 2(-1.375,0) 3(-1.375,-0.95) 4(1.375,-0.95) 5(1.375,0) 6(1.375,0.95)
  silkscreen extent -1.68,-1.55 0.5,1.55, body extent -1.42,-1.46 1.42,1.46, height 1.12
DDA0008J [mm] "SOIC, 8-Leads, Body 4.9x3.9mm, Pitch 1.27mm, Exposed Pad"
  rrect14% 1.55x0.6 smd: 1(-2.7,1.905) 2(-2.7,0.635) 3(-2.7,-0.635) 4(-2.7,-1.905) 5(2.7,-1.905) 6(2.7,-0.635) 7(2.7,0.635) 8(2.7,1.905)
  rrect4% 2.95x4.9 smd paste-1.5 mask-1.5: 9(0,0)
  silkscreen extent -3.47,-2.55 1.58,2.55, body extent -3.01,-2.45 3.01,2.45, height 1.57
DDC0006A_N [mm]
  rrect17% 1x0.6 smd: 1(-1.375,0.95) 2(-1.375,0) 3(-1.375,-0.95) 4(1.375,-0.95) 5(1.375,0) 6(1.375,0.95)
  silkscreen extent -1.75,-1.52 0.7,1.53, body extent -1.43,-1.48 1.43,1.49, height 0.92
DGK0008A_N [mm] "TSOP, 8-Leads, Body 3x3mm, Pitch 0.65mm, IPC Medium Density"
  oval 1.35x0.45 smd: 1(-2.225,0.975) 2(-2.225,0.325) 3(-2.225,-0.325) 4(-2.225,-0.975) 5(2.225,-0.975) 6(2.225,-0.325) 7(2.225,0.325) 8(2.225,0.975)
  silkscreen extent -2.75,-1.55 0.95,1.55, body extent -2.45,-1.5 2.45,1.5, height 0.96
DLC0008A [mm] "VSON-HR-8"
  rrect40% 0.55x0.25 smd: 1(-0.675,0.75) 2(-0.675,0.25) 3(-0.675,-0.25) 4(-0.675,-0.75) 5(0.675,-0.75) 6(0.675,-0.25) 7(0.675,0.25) 8(0.675,0.75)
  silkscreen extent -0.75,-1.15 0.75,1.15, body extent -0.8,-1.05 0.8,1.05, height 1.02
DQJ0008A [mm] "SMD, 8-Leads, Body 5.75x4.9mm"
  rrect39% 0.91x0.51 smd paste+0 mask+0.05: 1(-2.795,1.905) 2(-2.795,0.635) 3(-2.795,-0.635) 4(-2.795,-1.905) 5(2.795,-1.905) 6(2.795,-0.635) 7(2.795,0.635) 8(2.795,1.905)
  rrect8% 1.58x1.25 on Top Paste: 9(-0.38,1.45) 9(-0.38,0) 9(-0.38,-1.45) 9(1.4,-1.45) 9(1.4,0) 9(1.4,1.45)
  rrect3% 3.48x4.47 on Top Solder: 9(0.55,0)
  rrect2% 4.49x4.57 smd paste-2.5 mask-2.5: 9(1.005,0)
  silkscreen extent -3,-2.6 3,2.6, body extent -3.13,-2.45 3.13,2.45, height 1.15
DQK0006C [mm] "WSON"
  rrect12% 0.9x0.86 on Top Paste: 0(0,0.325)
  rrect34% 0.7x0.29 on Top Paste: 0(0.095,-0.65)
  rrect33% 0.45x0.3 smd: 1(-0.975,0.65) 2(-0.975,0) 3(-0.975,-0.65) 4(0.975,-0.65) 5(0.975,0) 6(0.975,0.65)
  rrect33% 0.75x0.3 smd paste-0.15: 7(0.095,-0.65)
  rrect11% 1x0.95 smd paste-0.5: 8(0,0.325)
  silkscreen extent -1.15,-1.15 1.15,1.15, body extent -1,-1 1,1, height 0.82
DRV0006A [mm] "SON, 6-Leads, Body 2x2mm, Pitch 0.65mm, Thermal Pad 1.6x1mm, TI Recommended"
  rrect33% 0.45x0.3 smd: 1(-0.975,0.65) 2(-0.975,0) 3(-0.975,-0.65) 4(0.975,-0.65) 5(0.975,0) 6(0.975,0.65)
  rrect14% 1x0.7 on Top Paste: 7(0,0.45) 7(0,-0.45)
  rrect10% 1x1.6 smd paste-0.5: 7(0,0)
  silkscreen extent -1.05,-1.2 1.05,1.2, body extent -1.05,-1.05 1.05,1.05, height 0.81
DSG0008A [mm] "SON, 8-Leads, Body 2x2mm, Pitch 0.5mm, Thermal Pad 1.6x0.9mm, TI Recommended"
  rrect40% 0.5x0.25 smd: 1(-0.95,0.75) 2(-0.95,0.25) 3(-0.95,-0.25) 4(-0.95,-0.75) 5(0.95,-0.75) 6(0.95,-0.25) 7(0.95,0.25) 8(0.95,0.75)
  rrect14% 0.9x0.7 on Top Paste: 9(0,0.45) 9(0,-0.45)
  rrect11% 0.9x1.6 smd paste-0.45: 9(0,0)
  silkscreen extent -1.07,-1.15 1.07,1.15, body extent -1,-1 1,1, height 0.77
FCC_disclaimer [mil]
FDSD0420 [mm] "SMD, 2-Leads, Body 4.2x4.2mm"
  rect 1.4x2.4 smd: 1(-1.6,0) 2(1.6,0)
  silkscreen extent -2.2,-2.2 2.2,2.2, body extent -2.1,-2.1 2.1,2.1, height 2
Fiducial10-20 [mm]
  round 1 smd mask+0.5: 1(0,0)
  Top Layer keep-out circle w1.178: c0,0 r0.5
Keystone5000 [mil] "For Keystone 500x miniature loop terminals"
  round 80 hole 40: 1(0,0)
  silkscreen extent -52,-52 52,52, body extent -49,-49 49,49, height 182
Keystone5001 [mil] "For Keystone 500x miniature loop terminals"
  round 80 hole 40: 1(0,0)
  silkscreen extent -52,-52 52,52, body extent -49,-49 49,49, height 182
Keystone_1902C [mil] "Hex Standoff, 4-40 threaded, nylon"
  round 1 on Mech4: 0(0,0)
  body extent -145,-126 146,126, height 501
"LG L29K_GREEN" [mm] "OSRAM"
  rect 0.8x0.8 smd paste-0.4: 1(-0.75,0) 2(0.75,0)
  silkscreen extent -0.1,-0.5 1.45,0.5, body extent -0.9,-0.45 0.9,0.45, height 0.67
LPS4018 [mil]
  rect 28x123 smd: 1(-72.5,0) 2(72.5,0)
  rect 35.5x28 smd rot 45: 1(-64,64) 2(64.5,-63.5)
  rect 35.5x28 smd rot 135: 1(-64,-64) 2(64,64)
  rect 31.5x28 smd: 1(-46,72.5) 1(-46,-72.5) 2(46,72.5) 2(46,-72.5)
  silkscreen extent -121,-102 101,102, body extent -81,-81 81,81, height 71
LQH5BPN_20 [mm] "MURATA"
  rrect5% 1.85x4.1 smd: 1(-1.825,0) 2(1.825,0)
  silkscreen extent -2.5,-2.65 2.5,2.65, body extent -2.55,-2.55 2.55,2.55, height 2.2
M_1000x2000 [mm] "Panasonic"
  rect 1.5x1.5 hole 0.9: 1(-2.5,0)
  round 1.5 hole 0.9: 2(2.5,0)
  silkscreen extent -5.3,-5.3 5.3,5.3, body extent -5.21,-5.24 5.24,5.24, height 22.01
NGU0008C [mm] "SON, 8-Leads, Body 4x4mm, Pitch 0.8mm"
  rrect33% 0.6x0.3 smd: 1(-1.9,1.2) 2(-1.9,0.4) 3(-1.9,-0.4) 4(-1.9,-1.2) 5(1.9,-1.2) 6(1.9,-0.4) 7(1.9,0.4) 8(1.9,1.2)
  rrect8% 1.75x1.31 on Top Paste: 9(0,-0.755) 9(0,0.755)
  rrect5% 1.98x3 smd paste-1.5: 9(0,0)
  silkscreen extent -2.15,-2.15 2.15,2.15, body extent -2,-2 2,2, height 0.77
"NY PMS 440 0025 PH" [mm] "4-40 nylon screw and mounting hole"
  round 8 hole 3.2: 1(0,0)
  body extent -3.3,-3.3 3.3,3.3, height 2.69
Pb-Free_Overlay_Small [mil]
  silkscreen extent -46,-46 46,46
RGE0024H [mm] "QFN, 24-Leads, Body 4x4mm, Pitch 0.5mm, Thermal Pad 2.7x2.7mm, TI Recommended"
  rrect42% 0.6x0.24 smd: 1(-1.9,1.25) 2(-1.9,0.75) 3(-1.9,0.25) 4(-1.9,-0.25) 5(-1.9,-0.75) 6(-1.9,-1.25) 13(1.9,-1.25) 14(1.9,-0.75) 15(1.9,-0.25) 16(1.9,0.25) 17(1.9,0.75) 18(1.9,1.25)
  rrect42% 0.24x0.6 smd: 7(-1.25,-1.9) 8(-0.75,-1.9) 9(-0.25,-1.9) 10(0.25,-1.9) 11(0.75,-1.9) 12(1.25,-1.9) 19(1.25,1.9) 20(0.75,1.9) 21(0.25,1.9) 22(-0.25,1.9) 23(-0.75,1.9) 24(-1.25,1.9)
  rrect8% 1.19x1.19 on Top Paste: 25(-0.695,-0.695) 25(-0.695,0.695) 25(0.695,-0.695) 25(0.695,0.695)
  rrect4% 2.7x2.7 smd paste-1.35: 25(0,0)
  silkscreen extent -2.22,-2.22 2.22,2.22, body extent -2.07,-2.07 2.07,2.07, height 1.01
SM_RADIAL_C [mm] "5 x 5.8mm:  Panasonic C"
  rect 2.8x1.6 smd: 1(-2.15,0) 2(2.15,0)
  silkscreen extent -2.75,-2.75 2.75,2.75, body extent -2.75,-2.75 2.75,2.75, height 6.1
SMA [mm] "Molded Diode, 2-Leads, Body 4.3x2.6mm, IPC Medium Density, based on OnSemi component dimensions and land pattern"
  rect 2x2 smd: 1(-2,0) 2(2,0)
  silkscreen extent -3.66,-1.57 2.79,1.57, body extent -2.6,-1.3 2.6,1.3, height 2.42
SMC [mil] "Molded Diode, 2-Leads, Body 6.9x5.8mm, IPC Medium Density, based on OnSemi component dimensions and land patterns"
  rect 110x150 smd: 1(-140.49,0) 2(140.49,0)
  silkscreen extent -221,-123 189,123, body extent -156,-116 156,116, height 91
SOD-123 [mm] "On Semi recommended land pattern"
  rect 0.915x1.22 smd: 1(-1.637,0) 2(1.637,0)
  silkscreen extent -2.74,-1.17 2.03,1.17, body extent -1.93,-0.9 1.93,0.9, height 1.35
SOD-128 [mm] "SMD, 2-Leads, Body 4x2.7mm, Height 1.1mm"
  rect 1.4x2.1 smd paste+0: 1(-2.2,0) 2(2.2,0)
  silkscreen extent -3.45,-1.45 2.95,1.45, body extent -2.5,-1.35 2.5,1.35, height 1.11
SRR1260 [mil] "Bourns UL"
  rect 114x213 smd: 1(-191,0) 2(191,0)
  silkscreen extent -252,-252 252,252, body extent -252,-252 252,252, height 236
TEC_282834-2 [mm] "TEC"
  rect 1.6x1.6 hole 1.1: 1(-1.27,0)
  round 1.6 hole 1.1: 2(1.27,0)
  silkscreen extent -3.73,-3.4 2.9,3.4, body extent -2.77,-3.25 2.77,3.25, height 10.01
WE-PDF_1064 [mm] "WERTH"
  rect 2.4x3.4 smd: 1(-4.1,0) 2(4.1,0)
  silkscreen extent -5.1,-5.1 5.1,5.1, body extent -5.1,-5.1 5.1,5.1, height 6.35
WE-SL5_HC [mm] "SMD, 4-Leads, Body 9.5x8.3mm"
  rect 2.7x2.7 smd: 1(-3.8,3.1) 2(-3.8,-3.1) 3(3.8,-3.1) 4(3.8,3.1)
  silkscreen extent -5.2,-4.15 4.75,4.15, body extent -4.75,-4.15 4.75,4.15, height 5.31
WEEE_Minimum [mil] "WEEElie bin"
  silkscreen extent -95,-172 99,104
WURTH_61300411121 [mm] "Header, 2.54mm, 4x1, TH"
  rect 1.65x1.65 hole 1.15: 1(-3.81,0)
  round 1.65 hole 1.15: 2(-1.27,0) 3(1.27,0) 4(3.81,0)
  silkscreen extent -5.08,-1.27 5.08,1.6, body extent -5.08,-1.27 5.08,1.27, height 8.54
Wurth_EFD15_4265 [mm] "SMD, 12-Leads, Body 22.35x17.78mm, Pitch 2.49mm"
  rrect9% 2.62x1.17 smd: 1(-9.895,6.225) 2(-9.895,3.735) 3(-9.895,1.245) 4(-9.895,-1.245) 5(-9.895,-3.735) 6(-9.895,-6.225) 7(9.895,-6.225) 8(9.895,-3.735) 9(9.895,-1.245) 10(9.895,1.245) 11(9.895,3.735) 12(9.895,6.225)
  body extent -10.62,-8.49 10.62,8.5, height 8.3
XFL4015 [mm] "SMD, 2-Leads, Body 4x4mm"
  rect 0.98x3.4 smd: 1(-1.185,0) 2(1.185,0)
  silkscreen extent -2.15,-2.15 2.15,2.15, body extent -2.15,-2.15 2.15,2.15, height 1.6

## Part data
C1 C2 C7 C16: library part CMP-0064935-4, "CAP, CERM, 0.1 uF, 100 V,+/- 10%, X7R, AEC-Q200 Grade 1, 0603", Cap_Case=0603, Manufacturer=MuRata, Supplier Part Number 1=490-13420-1-ND, TempCo=X7R, Tolerance_%=10%, Value1=Unknown, Value2=100V, ValueDisplayed=0.1uF
C3 C47: "CAP, CERM, 1 uF, 16 V, +/- 10%, X7R, 0603", Cap_Case=0603, Manufacturer="Wurth Elektronik", PartNumber=885012206052, Supplier Part Number 1=710-885012206052, TempCo=X7R, Tolerance_%=10%, Value1=Unknown, Value2=16V, ValueDisplayed=1uF
C4 C40: library part CMP-0008705-2, "CAP, CERM, 10 uF, 35 V, +/- 10%, X7R, 1206", Cap_Case=1206_180, Manufacturer=TDK, Supplier Part Number 1=445-14799-1-ND, TempCo=X7R, Tolerance_%=10%, Value1="0.002229 ohm", Value2=35V, ValueDisplayed=10uF
C5 C6 C12 C13 C14 C15: library part CMP-0009135-2, "CAP, CERM, 4.7 uF, 100 V, +/- 10%, X7S, 1210", Cap_Case=1210, Manufacturer=TDK, Supplier Part Number 1=445-8912-1-ND, TempCo=X7S, Tolerance_%=10%, Value1=Unknown, Value2=100V, ValueDisplayed=4.7uF
C8: library part CMP-0007891-2, "CAP, CERM, 1 uF, 100 V, +/- 10%, X7S, 0805", Cap_Case=0805, Manufacturer=TDK, Supplier Part Number 1=445-5205-1-ND, TempCo=X7S, Tolerance_%=10%, Value1="0.008255 ohm", Value2=100V, ValueDisplayed=1uF
C9: library part CMP-0006960-4, "CAP, CERM, 680 pF, 50 V, +/- 10%, X7R, 0603", Cap_Case=0603, Manufacturer=Kemet, Supplier Part Number 1=399-1077-1-ND, TempCo=X7R, Tolerance_%=10%, Value1=Unknown, Value2=50V, ValueDisplayed=680pF
C17: library part CMP-0008698-2, "CAP, CERM, 2.2 uF, 50 V, +/- 10%, X7R, 1206", Cap_Case=1206_180, Manufacturer=TDK, Supplier Part Number 1=445-7697-1-ND, TempCo=X7R, Tolerance_%=10%, Value1="0.005887 ohm", Value2=50V, ValueDisplayed=2.2uF
C18 C101: library part CMP-0009837-2, "CAP, AL, 470 uF, 50 V, +/- 20%, TH", Cap_Case=10x20mm, Manufacturer=Panasonic, Supplier Part Number 1=P5185-ND, Tolerance_%=20%, Value1=Unknown, Value2=50V, ValueDisplayed=470uF
C19: library part CMP-0007322-2, "CAP, CERM, 0.22 uF, 10 V, +/- 10%, X5R, 0603", Cap_Case=0603, Manufacturer=MuRata, PartNumber=GRM188R71C223KA01D, Supplier Part Number 1=490-1527-1-ND, TempCo=X7R, Tolerance_%=10%, Value1=Unknown, Value2=16V, ValueDisplayed=0.022uF
C20 C22 C26 C30 C32: library part CMP-0008702-2, "CAP, CERM, 4.7 uF, 50 V, +/- 10%, X7R, 1206", Cap_Case=1206_180, Manufacturer=TDK, Supplier Part Number 1=445-8032-1-ND, TempCo=X7R, Tolerance_%=10%, Value1="0.003158 ohm", Value2=50V, ValueDisplayed=4.7uF
C21: library part CMP-0007783-2, "CAP, CERM, 330 pF, 50 V, +/- 10%, X7R, 0805", Cap_Case=0805, Manufacturer=Kemet, Supplier Part Number 1=399-1140-1-ND, TempCo=X7R, Tolerance_%=10%, Value1="0.935 ohm", Value2=50V, ValueDisplayed=330pF
C23: library part CMP-0079247-1, "CAP, CERM, 4700 pF, 100 V,+/- 10%, X7R, AEC-Q200 Grade 1, 0603", Cap_Case=0603, Manufacturer=MuRata, Supplier Part Number 1=490-4930-1-ND, TempCo=X7R, Tolerance_%=10%, Value2=100V, ValueDisplayed=4700pF
C24: library part CMP-0011174-2, "CAP, AL, 4.7 uF, 50 V, +/- 20%, 3 ohm, SMD", Cap_Case=C, Manufacturer=Panasonic, Supplier Part Number 1=PCE4021CT-ND, Tolerance_%=20%, Value1="3 ohm", Value2=50V, ValueDisplayed=4.7uF
C25: library part CMP-0007453-4, "CAP, CERM, 3900 pF, 50 V, +/- 10%, X7R, 0603", Cap_Case=0603, Manufacturer=MuRata, Supplier Part Number 1=490-1504-1-ND, TempCo=X7R, Tolerance_%=10%, Value1=Unknown, Value2=50V, ValueDisplayed=3900pF
C27 C28 C29 C57: library part CMP-0008802-2, "CAP, CERM, 10 uF, 50 V, +/- 10%, X7R, 1206", Cap_Case=1206, Manufacturer=Samsung, Supplier Part Number 1=1276-6767-1-ND, TempCo=X7R, Tolerance_%=10%, Value1=Unknown, Value2=50V, ValueDisplayed=10uF
C31 C58: library part CMP-0007730-2, "CAP, CERM, 1 uF, 50 V, +/- 10%, X7R, 0805", Cap_Case=0805, Manufacturer=Kemet, Supplier Part Number 1=399-7409-1-ND, TempCo=X7R, Tolerance_%=10%, Value1=Unknown, Value2=50V, ValueDisplayed=1uF
C33: library part CMP-0008315-2, "CAP, CERM, 10 uF, 10 V, +/- 10%, X7R, 0805", Cap_Case=0805, Manufacturer=MuRata, Supplier Part Number 1=490-3905-1-ND, TempCo=X7R, Tolerance_%=10%, Value1="0.003 ohm", Value2=10V, ValueDisplayed=10uF
C34 C50: "CAP, CERM, 4.7 uF, 35 V, +/- 10%, X7R, 0805", Cap_Case=0805, Manufacturer=TDK, PartNumber=C2012X7R1V475K125AC, Supplier Part Number 1=445-7555-1-ND, TempCo=X7R, Tolerance_%=10%, Value1="0.002346 ohm", Value2=35V, ValueDisplayed=4.7uF
C35 C39 C42 C43 C44 C45 C49: library part CMP-0008805-2, "CAP, CERM, 22 uF, 16 V, +/- 20%, X7R, 1206_190", Cap_Case=1206, Manufacturer="Taiyo Yuden", Supplier Part Number 1=587-4319-1-ND, TempCo=X7R, Tolerance_%=20%, Value1=Unknown, Value2=16V, ValueDisplayed=22uF
C36: "CAP, CERM, 0.1 uF, 50 V, +/- 10%, X7R, 0603", Cap_Case=0603, Manufacturer=TDK, PartNumber=C1608X7R1H104K080AA, Supplier Part Number 1=445-1314-1-ND, TempCo=X7R, Tolerance_%=10%, Value1="0.0296 ohm", Value2=50V, ValueDisplayed=0.1uF
C37 C48: library part CMP-0009765-1, "CAP, CERM, 120 pF, 25 V, +/- 10%, X7R, 0201", Cap_Case=0201, Manufacturer=MuRata, Supplier Part Number 1=490-3173-1-ND, TempCo=X7R, Tolerance_%=10%, Value1=Unknown, Value2=25V, ValueDisplayed=120pF
C38: library part CMP-0081201-1, "CAP, CERM, 4.7 µF, 35 V,+/- 10%, X7R, AEC-Q200 Grade 1, 1206", Cap_Case=1206, Manufacturer=TDK, Supplier Part Number 1=445-8805-1-ND, TempCo=X7R, Tolerance_%=10%, Value2=35V, ValueDisplayed=4.7µF
C46: library part CMP-0007119-4, "CAP, CERM, 0.1 uF, 16 V, +/- 10%, X7R, 0603", Cap_Case=0603, Manufacturer="Taiyo Yuden", Supplier Part Number 1=587-1240-1-ND, TempCo=X7R, Tolerance_%=10%, Value1=Unknown, Value2=16V, ValueDisplayed=0.1uF
C51: library part CMP-0009026-2, "CAP, CERM, 4.7 uF, 50 V, +/- 10%, X7R, 1206_190", Cap_Case=1206, Manufacturer="Taiyo Yuden", Supplier Part Number 1=587-2994-2-ND, TempCo=X7R, Tolerance_%=10%, Value1=Unknown, Value2=50V, ValueDisplayed=4.7uF
C55 C56: library part CMP-0007094-5, "CAP, CERM, 0.22 uF, 50 V, +/- 10%, X7R, AEC-Q200 Grade 1, 0603", Cap_Case=0603, Manufacturer=TDK, Supplier Part Number 1=445-6926-1-ND, TempCo=X7R, Tolerance_%=10%, Value1="0.021699 ohm", Value2=50V, ValueDisplayed=0.22uF
D1: library part CMP-0005697-2, "Diode, TVS, Bi, 36 V, 58.1 Vc, SMC", Manufacturer=Littelfuse, Power_W=6.5W, Supplier Part Number 1=SMCJ36CALFCT-ND
D2: library part CMP-0081099-1, "Diode, Schottky, 100 V, 2 A, SMA", Manufacturer="Diodes Inc.", Supplier Part Number 1=B2100A-13-FDICT-ND, Value1=2A, Value2=0.79V
D3 D4 D5 D6: library part CMP-0028783-2, "Diode, Schottky, 100 V, 3 A, AEC-Q101, SOD-128", Manufacturer=Nexperia, Supplier Part Number 1=568-12696-1-ND, Value1=3A, Value2=0.77V
D7: library part CMP-0028526-2, "Diode, Schottky, 40 V, 0.5 A, SOD-123", Manufacturer="ON Semiconductor", Value1=0.5A, Value2=0.51V
FID1 FID2 FID3 FID4 FID5 FID6: library part CMP-0077181-1, "Fiducial mark.  There is nothing to buy or mount.", Manufacturer=N/A
H1 H2 H3 H4: library part CMP-0003617-1, "Machine Screw, Round, #4-40 x 1/4, Nylon, Philips panhead", Manufacturer="B&F Fastener Supply", Supplier Part Number 1=H542-ND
